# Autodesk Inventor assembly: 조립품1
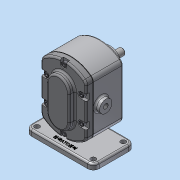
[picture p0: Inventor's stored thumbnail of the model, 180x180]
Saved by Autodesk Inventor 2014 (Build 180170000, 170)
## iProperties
Created: 2019-03
Part Number: 조립품1
Document SubType Name: Assembly
Designer: NET
Author: NET
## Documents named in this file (11)
- C:\Users\NET\Desktop\490307V1046\조립품1.iam
- C:\Users\NET\Desktop\490307V1046\부품1.ipt
- C:\Users\NET\Desktop\490307V1046\개스킷.ipt
- C:\Users\NET\Desktop\490307V1046\메인축.ipt
- C:\Users\NET\Desktop\490307V1046\베어링부시.ipt
- C:\Users\NET\Desktop\490307V1046\서브축.ipt
- C:\Users\NET\Desktop\490307V1046\스퍼기어.ipt
- C:\Users\NET\Desktop\490307V1046\오일 실 16 28 7.ipt
- C:\Users\NET\Desktop\490307V1046\커버.ipt
- C:\Users\NET\Desktop\490307V1046\키 6 x 6 x 18.ipt
- C:\Users\NET\Desktop\490307V1046\볼트 M5.ipt
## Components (1 placed, 1 different names)
1. 개스킷:1
